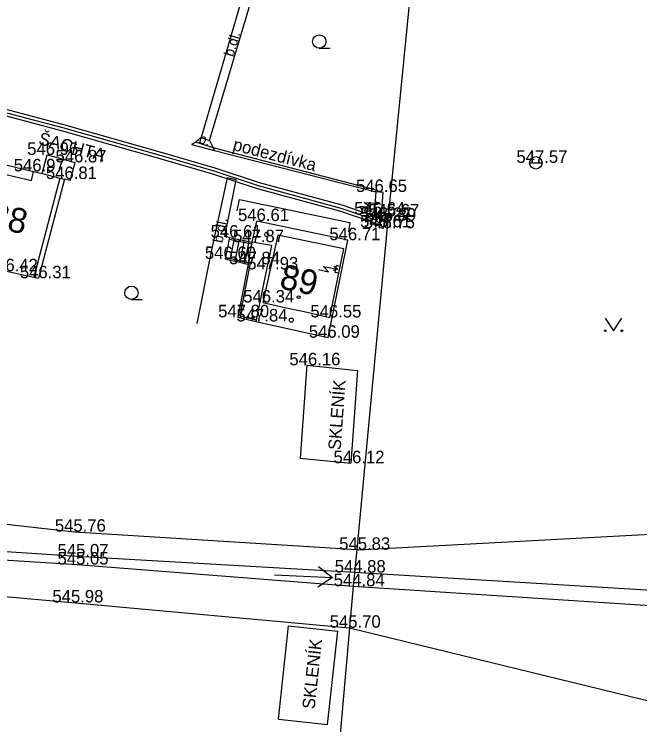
# Model space of a CAD drawing. Extents: x -669995 to -669686, y -1125551 to -1125263.
# Drawn here: x -669770.25 to -669732.62, y -1125382.34 to -1125339.58 of the extents above; entities that cross this region are included whole.
import ezdxf

# ---------------------------------------------------------------- set-up
doc = ezdxf.new("R2010")
doc.units = 0
for name, color, linetype in [('G_Bod_tecka', 7, 'Continuous'), ('G_Bod_vyska', 7, 'Continuous'), ('G_Breh_Teren', 7, 'Continuous'), ('G_Budovy-znacky', 7, 'Continuous'), ('G_Budovy_Objekty', 7, 'Continuous'), ('G_Budovy_vstupy', 7, 'Continuous'), ('G_Cesty_Schody', 7, 'Continuous'), ('G_Cisla_popisna', 7, 'Continuous'), ('G_Objekty-Studny', 7, 'Continuous'), ('G_Plochy_zpevnene', 7, 'Continuous'), ('G_Ploty', 7, 'Continuous'), ('G_Popisy_Nazvy', 7, 'Continuous'), ('G_Popisy_povrchu', 7, 'Continuous'), ('G_Poznamky_odkaz', 7, 'Continuous'), ('G_Site-Rozvadece', 7, 'Continuous'), ('G_Site-Sloupy', 7, 'Continuous'), ('G_Z_CHRANICKA-TEPLOVOD_kotovane', 7, 'Continuous'), ('G_Z_ELsilove_podz_kotovane', 7, 'Continuous'), ('G_Zabradli_Svodidla', 7, 'Continuous'), ('G_Zelen-Znacky', 7, 'Continuous')]:
    doc.layers.add(name, color=color, linetype=linetype)

msp = doc.modelspace()

# ---------------------------------------------------------------- linework, layer by layer
at = {"layer": 'G_Bod_tecka'}
for p, q in [((-669768.28, -1125348.05), (-669768.28, -1125348.05)), ((-669766.59, -1125348.5), (-669766.59, -1125348.5)), ((-669738.88, -1125348.53), (-669738.88, -1125348.53)), ((-669769.1, -1125349.04), (-669769.1, -1125349.04)), ((-669767.23, -1125349.5), (-669767.23, -1125349.5)), ((-669748.5, -1125350.28), (-669748.5, -1125350.28)), ((-669748.61, -1125351.64), (-669748.61, -1125351.64)), ((-669755.66, -1125352.03), (-669755.66, -1125352.03)), ((-669748.24, -1125351.96), (-669748.24, -1125351.96)), ((-669747.96, -1125352.01), (-669747.96, -1125352.01)), ((-669747.76, -1125351.75), (-669747.76, -1125351.75)), ((-669748.32, -1125352.41), (-669748.32, -1125352.41)), ((-669748.04, -1125352.46), (-669748.04, -1125352.46)), ((-669757.31, -1125353.02), (-669757.31, -1125353.02)), ((-669755.93, -1125353.3), (-669755.93, -1125353.3)), ((-669750.18, -1125353.18), (-669750.18, -1125353.18)), ((-669757.57, -1125354.31), (-669757.57, -1125354.31)), ((-669756.17, -1125354.63), (-669756.17, -1125354.63)), ((-669755.07, -1125354.94), (-669755.07, -1125354.94)), ((-669768.8, -1125355.47), (-669768.8, -1125355.47)), ((-669755.3, -1125356.93), (-669755.3, -1125356.93)), ((-669756.8, -1125357.82), (-669756.8, -1125357.82)), ((-669751.26, -1125357.83), (-669751.26, -1125357.83)), ((-669755.72, -1125358.07), (-669755.72, -1125358.07)), ((-669751.33, -1125359.05), (-669751.33, -1125359.05)), ((-669752.65, -1125360.71), (-669752.65, -1125360.71)), ((-669750.01, -1125366.6), (-669750.01, -1125366.6)), ((-669766.63, -1125370.72), (-669766.63, -1125370.72)), ((-669749.54, -1125371.81), (-669749.54, -1125371.81)), ((-669766.46, -1125372.21), (-669766.46, -1125372.21)), ((-669766.46, -1125372.7), (-669766.46, -1125372.7)), ((-669749.81, -1125373.18), (-669749.81, -1125373.18)), ((-669749.87, -1125374), (-669749.87, -1125374)), ((-669766.79, -1125374.98), (-669766.79, -1125374.98)), ((-669750.09, -1125376.5), (-669750.09, -1125376.5))]:
    msp.add_line(p, q, dxfattribs=at)
at = {"layer": 'G_Breh_Teren'}
for p, q in [((-669787.86, -1125368.33), (-669766.63, -1125370.72)), ((-669766.63, -1125370.72), (-669749.65, -1125371.8)), ((-669749.54, -1125371.81), (-669729.04, -1125370.72)), ((-669749.65, -1125371.8), (-669749.54, -1125371.81)), ((-669788.48, -1125373.02), (-669766.79, -1125374.98)), ((-669766.79, -1125374.98), (-669750.09, -1125376.5)), ((-669750.09, -1125376.5), (-669730.69, -1125381.25))]:
    msp.add_line(p, q, dxfattribs=at)
for points in [[(-669818.35, -1125369.39), (-669807.42, -1125370.05), (-669788.12, -1125371.33), (-669766.46, -1125372.7), (-669749.86, -1125374)], [(-669749.78, -1125373.18), (-669766.46, -1125372.21), (-669788.15, -1125370.79), (-669807.36, -1125369.51), (-669811.67, -1125369.18)], [(-669724.95, -1125374.69), (-669749.78, -1125373.18)], [(-669749.86, -1125374), (-669725.2, -1125375.61)]]:
    msp.add_lwpolyline(points, dxfattribs=at)
at = {"layer": 'G_Budovy-znacky'}
for centre, radius in [((-669755.07, -1125352.84), 0.125), ((-669753.149, -1125356.61), 0.0875), ((-669753.581, -1125357.99), 0.125)]:
    msp.add_circle(centre, radius, dxfattribs=at)
at = {"layer": 'G_Budovy_Objekty'}
for p, q in [((-669771.63, -1125348.45), (-669769.1, -1125349.04)), ((-669771.62, -1125349.02), (-669769.22, -1125349.58)), ((-669769.22, -1125349.58), (-669769.1, -1125349.04)), ((-669769.1, -1125349.04), (-669768.58, -1125349.17)), ((-669767.5, -1125349.44), (-669769.08, -1125355.41)), ((-669767.23, -1125349.5), (-669768.8, -1125355.47)), ((-669768.58, -1125349.17), (-669767.5, -1125349.44)), ((-669767.5, -1125349.44), (-669767.23, -1125349.5)), ((-669755.93, -1125353.3), (-669755.66, -1125352.03)), ((-669750.18, -1125353.18), (-669755.66, -1125352.03)), ((-669754.39, -1125352.87), (-669755.3, -1125356.93)), ((-669750.43, -1125353.7), (-669754.39, -1125352.87)), ((-669756.17, -1125354.63), (-669755.93, -1125353.3)), ((-669754.78, -1125353.51), (-669755.93, -1125353.3)), ((-669751.36, -1125359.04), (-669750.18, -1125353.18)), ((-669754.78, -1125353.51), (-669754.9, -1125354.11)), ((-669750.64, -1125354.76), (-669750.43, -1125353.7)), ((-669756.17, -1125354.63), (-669756.8, -1125357.82)), ((-669770.72, -1125355.05), (-669769.08, -1125355.41)), ((-669755.07, -1125354.94), (-669755.72, -1125358.07)), ((-669750.72, -1125355.15), (-669750.64, -1125354.76)), ((-669769.08, -1125355.41), (-669768.8, -1125355.47)), ((-669751.26, -1125357.83), (-669750.72, -1125355.15)), ((-669755.3, -1125356.93), (-669753.7, -1125357.29)), ((-669752.82, -1125357.48), (-669751.26, -1125357.83)), ((-669756.8, -1125357.82), (-669755.72, -1125358.07)), ((-669755.72, -1125358.07), (-669751.36, -1125359.04))]:
    msp.add_line(p, q, dxfattribs=at)
at = {"layer": 'G_Budovy_vstupy'}
for p, q in [((-669754.9, -1125354.11), (-669755.07, -1125354.94)), ((-669753.7, -1125357.29), (-669752.82, -1125357.48))]:
    msp.add_line(p, q, dxfattribs=at)
at = {"layer": 'G_Cesty_Schody'}
for p, q in [((-669759.01, -1125347), (-669758.51, -1125347.19)), ((-669758.2, -1125347.78), (-669758.29, -1125347.63)), ((-669768.58, -1125349.17), (-669768.28, -1125348.05)), ((-669768.28, -1125348.05), (-669766.59, -1125348.5)), ((-669766.88, -1125349.59), (-669766.59, -1125348.5)), ((-669766.88, -1125349.59), (-669767.23, -1125349.5)), ((-669757.31, -1125353.02), (-669757.57, -1125354.31)), ((-669757.31, -1125353.02), (-669757.02, -1125353.08)), ((-669757.02, -1125353.08), (-669757.28, -1125354.38)), ((-669757.02, -1125353.08), (-669756.72, -1125353.14)), ((-669756.72, -1125353.14), (-669756.98, -1125354.44)), ((-669756.72, -1125353.14), (-669756.43, -1125353.2)), ((-669756.43, -1125353.2), (-669756.69, -1125354.51)), ((-669756.43, -1125353.2), (-669756.13, -1125353.26)), ((-669756.13, -1125353.26), (-669756.4, -1125354.58)), ((-669756.13, -1125353.26), (-669755.93, -1125353.3)), ((-669757.57, -1125354.31), (-669757.28, -1125354.38)), ((-669757.28, -1125354.38), (-669756.98, -1125354.44)), ((-669756.98, -1125354.44), (-669756.69, -1125354.51)), ((-669756.69, -1125354.51), (-669756.4, -1125354.58)), ((-669756.4, -1125354.58), (-669756.17, -1125354.63)), ((-669752.65, -1125360.71), (-669753.06, -1125366.29)), ((-669752.65, -1125360.71), (-669749.6, -1125361.02)), ((-669749.6, -1125361.02), (-669750.01, -1125366.6)), ((-669753.06, -1125366.29), (-669750.01, -1125366.6)), ((-669754.36, -1125382), (-669753.76, -1125376.38)), ((-669753.76, -1125376.38), (-669750.79, -1125376.7)), ((-669751.4, -1125382.32), (-669750.79, -1125376.7)), ((-669754.36, -1125382), (-669751.4, -1125382.32))]:
    msp.add_line(p, q, dxfattribs=at)
at = {"layer": 'G_Objekty-Studny'}
msp.add_line((-669739.255, -1125348.53), (-669738.505, -1125348.53), dxfattribs=at)
msp.add_circle((-669738.88, -1125348.53), 0.375, dxfattribs=at)
at = {"layer": 'G_Plochy_zpevnene'}
for p, q in [((-669754.88, -1125332.92), (-669759.01, -1125347)), ((-669758.51, -1125347.19), (-669754.32, -1125333.1)), ((-669759.01, -1125347), (-669759.33, -1125347.28)), ((-669758.51, -1125347.19), (-669758.29, -1125347.63))]:
    msp.add_line(p, q, dxfattribs=at)
msp.add_lwpolyline([(-669757.31, -1125353.02), (-669757.59, -1125352.96), (-669756.9, -1125349.54), (-669757.45, -1125349.42), (-669758.43, -1125353.96), (-669759.27, -1125358.19)], dxfattribs=at)
at = {"layer": 'G_Ploty'}
for p, q in [((-669745.42, -1125328.01), (-669747.76, -1125351.75)), ((-669759.33, -1125347.28), (-669759.59, -1125347.42)), ((-669758.29, -1125347.63), (-669759.33, -1125347.28)), ((-669759.59, -1125347.42), (-669758.2, -1125347.78)), ((-669748.49, -1125350.17), (-669758.29, -1125347.63)), ((-669758.2, -1125347.78), (-669748.5, -1125350.28)), ((-669748.5, -1125350.28), (-669748.49, -1125350.17)), ((-669747.76, -1125351.75), (-669749.65, -1125371.8)), ((-669748.24, -1125351.96), (-669748.32, -1125352.41)), ((-669747.96, -1125352.01), (-669748.24, -1125351.96)), ((-669748.04, -1125352.46), (-669747.96, -1125352.01)), ((-669748.32, -1125352.41), (-669748.04, -1125352.46)), ((-669749.65, -1125371.8), (-669749.78, -1125373.18)), ((-669749.78, -1125373.18), (-669749.86, -1125374)), ((-669749.86, -1125374), (-669750.09, -1125376.5)), ((-669750.09, -1125376.5), (-669751.65, -1125394.45))]:
    msp.add_line(p, q, dxfattribs=at)
msp.add_lwpolyline([(-669756.85, -1125351.41), (-669756.7, -1125350.73), (-669750.06, -1125352.11), (-669750.14, -1125352.68)], dxfattribs=at)
at = {"layer": 'G_Popisy_Nazvy'}
for p, q in [((-669751.94, -1125372.81), (-669751.1, -1125373.47)), ((-669754.597, -1125373.312), (-669751.1, -1125373.47)), ((-669751.1, -1125373.47), (-669751.997, -1125374.051))]:
    msp.add_line(p, q, dxfattribs=at)
at = {"layer": 'G_Site-Rozvadece'}
for p, q in [((-669749.473, -1125351.139), (-669748.849, -1125351.189)), ((-669748.849, -1125351.189), (-669749.202, -1125350.909)), ((-669749.202, -1125350.909), (-669748.33, -1125350.979)), ((-669748.583, -1125351.069), (-669748.33, -1125350.979)), ((-669748.33, -1125350.979), (-669748.565, -1125350.851)), ((-669751.953, -1125354.953), (-669751.339, -1125355.076)), ((-669751.339, -1125355.076), (-669751.658, -1125354.757)), ((-669751.658, -1125354.757), (-669750.8, -1125354.93)), ((-669751.062, -1125354.989), (-669750.8, -1125354.93)), ((-669750.8, -1125354.93), (-669751.018, -1125354.774)), ((-669750.89, -1125354.71), (-669750.96, -1125355.1)), ((-669750.64, -1125354.76), (-669750.89, -1125354.71)), ((-669750.96, -1125355.1), (-669750.72, -1125355.15))]:
    msp.add_line(p, q, dxfattribs=at)
msp.add_lwpolyline([(-669748.5, -1125350.28), (-669748.61, -1125351.64), (-669748.16, -1125351.68), (-669748.05, -1125350.32)], close=True, dxfattribs=at)
at = {"layer": 'G_Site-Sloupy'}
for radius in [0.25, 0.05]:
    msp.add_circle((-669747.86, -1125351.87), radius, dxfattribs=at)
at = {"layer": 'G_Z_CHRANICKA-TEPLOVOD_kotovane'}
msp.add_lwpolyline([(-669778.558, -1125343.397), (-669778.491, -1125343.412), (-669775.013, -1125344.196), (-669771.449, -1125345.117), (-669767.297, -1125346.217), (-669761.355, -1125347.898), (-669758.181, -1125348.819), (-669755.512, -1125349.708), (-669750.542, -1125351.059), (-669748.392, -1125351.786), (-669748.139, -1125352.039), (-669748.421, -1125352.321), (-669748.608, -1125352.134), (-669750.658, -1125351.441), (-669755.628, -1125350.091), (-669758.299, -1125349.201), (-669761.465, -1125348.282), (-669767.403, -1125346.603), (-669771.551, -1125345.503), (-669775.107, -1125344.584), (-669778.556, -1125343.807), (-669778.646, -1125343.787), (-669778.603, -1125343.596), (-669778.601, -1125343.589)], close=True, dxfattribs=at)
at = {"layer": 'G_Z_ELsilove_podz_kotovane'}
msp.add_lwpolyline([(-669778.93, -1125344.44), (-669778.7, -1125343.57), (-669775.06, -1125344.39), (-669771.5, -1125345.31), (-669767.35, -1125346.41), (-669761.41, -1125348.09), (-669758.24, -1125349.01), (-669755.57, -1125349.9), (-669750.6, -1125351.25), (-669749.128, -1125351.748), (-669748.879, -1125351.832), (-669748.5, -1125351.96), (-669748.28, -1125352.18)], dxfattribs=at)
at = {"layer": 'G_Zabradli_Svodidla'}
for p, q in [((-669757.33, -1125353.12), (-669755.95, -1125353.4)), ((-669757.55, -1125354.21), (-669756.05, -1125354.56)), ((-669756.05, -1125354.56), (-669756.68, -1125357.74)), ((-669756.68, -1125357.74), (-669755.7, -1125357.97))]:
    msp.add_line(p, q, dxfattribs=at)
at = {"layer": 'G_Zelen-Znacky'}
for p, q in [((-669751.902, -1125341.63), (-669751.252, -1125341.627)), ((-669763.202, -1125356.75), (-669762.552, -1125356.747)), ((-669734.7, -1125357.88), (-669734.2, -1125358.63)), ((-669734.2, -1125358.63), (-669733.7, -1125357.88))]:
    msp.add_line(p, q, dxfattribs=at)
for centre, radius in [((-669751.902, -1125341.227), 0.403), ((-669763.202, -1125356.347), 0.403), ((-669734.7, -1125358.63), 0.05), ((-669733.7, -1125358.63), 0.05)]:
    msp.add_circle(centre, radius, dxfattribs=at)

# ---------------------------------------------------------------- texts
at = {"layer": 'G_Bod_vyska'}
for s, p in [('546.96', (-669769.473, -1125348.05)), ('546.87', (-669767.768, -1125348.5)), ('547.57', (-669740.044, -1125348.53)), ('546.97', (-669770.28, -1125349.04)), ('546.81', (-669768.346, -1125349.5)), ('546.65', (-669749.692, -1125350.28)), ('546.64', (-669749.802, -1125351.64)), ('546.27', (-669749.418, -1125351.96)), ('546.67', (-669748.952, -1125351.75)), ('546.61', (-669756.79, -1125352.03)), ('546.89', (-669749.14, -1125352.01)), ('546.61', (-669749.45, -1125352.41)), ('546.75', (-669749.218, -1125352.46)), ('546.61', (-669758.44, -1125353.02)), ('546.71', (-669751.296, -1125353.18)), ('547.87', (-669757.094, -1125353.3)), ('546.60', (-669758.783, -1125354.31)), ('547.84', (-669757.334, -1125354.63)), ('547.93', (-669756.236, -1125354.94)), ('546.42', (-669771.898, -1125355.05)), ('546.31', (-669769.916, -1125355.47)), ('546.34', (-669756.478, -1125356.93)), ('547.80', (-669757.986, -1125357.82)), ('546.55', (-669752.438, -1125357.83)), ('547.84', (-669756.884, -1125358.07)), ('546.09', (-669752.531, -1125359.05)), ('546.16', (-669753.7, -1125360.71)), ('546.12', (-669751.046, -1125366.6)), ('545.76', (-669767.808, -1125370.72)), ('545.83', (-669750.704, -1125371.81)), ('545.07', (-669767.646, -1125372.21)), ('545.05', (-669767.646, -1125372.7)), ('544.88', (-669750.974, -1125373.18)), ('544.84', (-669751.034, -1125374)), ('545.98', (-669767.956, -1125374.98)), ('545.70', (-669751.276, -1125376.5))]:
    msp.add_text(s, height=0.75, dxfattribs=at).set_placement(p)
at = {"layer": 'G_Cisla_popisna'}
for s, rotation, p in [('88', 346.8731, (-669771.831, -1125352.334)), ('89', 347.4219, (-669754.36, -1125356.056))]:
    msp.add_text(s, height=1.5, rotation=rotation, dxfattribs=at).set_placement(p)
at = {"layer": 'G_Popisy_povrchu'}
for s, rotation, p in [('b.dl.', 73.4389, (-669757.076, -1125342.182)), ('b.', 341.3999, (-669759.199, -1125347.309)), ('b.dl.', 78.5934, (-669757.724, -1125353.38))]:
    msp.add_text(s, height=0.6, rotation=rotation, dxfattribs=at).set_placement(p)
at = {"layer": 'G_Poznamky_odkaz'}
for s, rotation, p in [('ŠACHTA', 345.0897, (-669768.843, -1125347.395)), ('podezdívka', 345.4696, (-669757.152, -1125347.75)), ('SKLENÍK', 85.7976, (-669750.62, -1125365.829)), ('SKLENÍK', 83.8524, (-669752.184, -1125381.422))]:
    msp.add_text(s, height=0.75, rotation=rotation, dxfattribs=at).set_placement(p)

doc.saveas('drawing.dxf')
